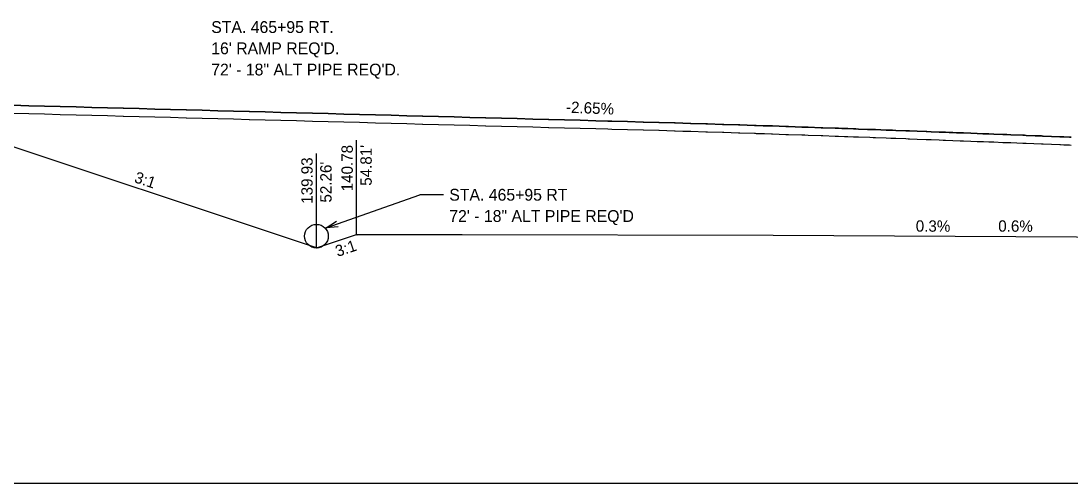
# Model space of a CAD drawing. Extents: x -26 to 4403, y -13 to 9578.
# Drawn here: x 1283.5 to 1350.1, y 7500 to 7529.3 of the extents above; entities that cross this region are included whole.
import ezdxf

# ---------------------------------------------------------------- set-up
doc = ezdxf.new("R2010")
doc.units = 0
for name, color, linetype in [('CONST_DCH', 7, 'Continuous'), ('CONST_LV3', 7, 'Continuous'), ('DTM_CORRIDOR', 7, 'Continuous'), ('DTM_P_FINISHED_GRADE', 7, 'Continuous'), ('DTM_X_GROUND', 7, 'Continuous'), ('XS_CELL', 7, 'Continuous'), ('XS_P_DR_GRAVEL', 7, 'Continuous'), ('XS_P_DRAINAGE', 7, 'Continuous'), ('XS_P_GROUND', 7, 'Continuous'), ('XS_P_TX_CLEARZONE', 7, 'Continuous'), ('XS_P_TX_FS_BS', 7, 'Continuous')]:
    doc.layers.add(name, color=color, linetype=linetype)

msp = doc.modelspace()

# ---------------------------------------------------------------- linework, layer by layer
at = {"layer": 'CONST_LV3'}
msp.add_lwpolyline([(1282.996, 7523.989), (1283.996, 7523.963), (1284.996, 7523.936), (1285.996, 7523.91), (1286.996, 7523.883), (1287.996, 7523.857), (1288.996, 7523.83), (1289.996, 7523.804), (1290.996, 7523.777), (1291.996, 7523.751), (1292.996, 7523.724), (1293.996, 7523.698), (1294.996, 7523.671), (1295.996, 7523.645), (1296.996, 7523.618), (1297.996, 7523.592), (1298.996, 7523.565), (1299.996, 7523.539), (1300.996, 7523.512), (1301.996, 7523.486), (1302.996, 7523.459), (1303.996, 7523.433), (1304.996, 7523.406), (1305.996, 7523.38), (1306.996, 7523.353), (1307.996, 7523.327), (1308.996, 7523.3), (1309.996, 7523.274), (1310.996, 7523.247), (1311.996, 7523.221), (1312.996, 7523.194), (1313.996, 7523.168), (1314.996, 7523.141), (1315.996, 7523.115), (1316.996, 7523.088), (1317.996, 7523.062), (1318.996, 7523.035), (1319.996, 7523.009), (1320.757, 7522.989), (1320.996, 7522.982), (1320.996, 7522.982), (1320.996, 7522.982), (1321.996, 7522.955), (1321.996, 7522.955), (1321.998, 7522.955), (1322.995, 7522.927), (1322.998, 7522.927), (1323.002, 7522.927), (1323.994, 7522.899), (1324.001, 7522.899), (1324.007, 7522.898), (1324.991, 7522.869), (1325.005, 7522.869), (1325.014, 7522.869), (1325.025, 7522.869), (1326.004, 7522.839), (1326.015, 7522.839), (1326.021, 7522.839), (1326.504, 7522.824), (1326.546, 7522.823), (1327.029, 7522.808), (1327.079, 7522.806), (1328.037, 7522.776), (1328.047, 7522.776), (1328.104, 7522.774), (1329.044, 7522.743), (1329.071, 7522.743), (1329.132, 7522.741), (1330.051, 7522.711), (1330.103, 7522.709), (1330.105, 7522.709), (1330.161, 7522.707), (1331.056, 7522.677), (1331.142, 7522.675), (1331.192, 7522.673), (1331.632, 7522.658), (1331.753, 7522.654), (1332.189, 7522.639), (1332.223, 7522.638), (1333.062, 7522.609), (1333.247, 7522.603), (1333.255, 7522.603), (1333.46, 7522.596), (1334.287, 7522.566), (1334.296, 7522.566), (1334.405, 7522.562), (1335.187, 7522.534), (1335.319, 7522.529), (1335.394, 7522.527), (1335.597, 7522.52), (1336.35, 7522.493), (1336.486, 7522.488), (1336.668, 7522.482), (1337.031, 7522.468), (1337.239, 7522.461), (1337.592, 7522.448), (1337.741, 7522.443), (1338.409, 7522.417), (1338.713, 7522.407), (1338.815, 7522.404), (1339.032, 7522.395), (1339.657, 7522.371), (1339.813, 7522.365), (1339.889, 7522.364), (1340.461, 7522.341), (1340.964, 7522.322), (1341.006, 7522.321), (1341.52, 7522.301), (1342.038, 7522.281), (1342.179, 7522.276), (1342.418, 7522.267), (1342.89, 7522.249), (1343.113, 7522.24), (1343.32, 7522.232), (1343.79, 7522.215), (1344.186, 7522.199), (1344.546, 7522.185), (1344.589, 7522.184), (1344.928, 7522.171), (1345.257, 7522.157), (1345.828, 7522.135), (1346.066, 7522.127), (1346.328, 7522.116), (1347.092, 7522.086), (1347.205, 7522.083), (1347.397, 7522.075), (1348.345, 7522.035), (1348.384, 7522.035), (1348.444, 7522.032), (1349.459, 7521.991), (1349.484, 7521.99), (1349.704, 7521.982), (1350.05, 7521.968), (1350.15, 7521.964)], dxfattribs=at)
at = {"layer": 'DTM_P_FINISHED_GRADE'}
msp.add_lwpolyline([(1283, 7523.989), (1283.996, 7523.963), (1284, 7523.963), (1284.996, 7523.936), (1285, 7523.936), (1285.996, 7523.91), (1286, 7523.91), (1286.996, 7523.883), (1287, 7523.883), (1287.996, 7523.857), (1288, 7523.857), (1288.996, 7523.83), (1289, 7523.83), (1289.996, 7523.804), (1290, 7523.804), (1290.996, 7523.777), (1291, 7523.777), (1291.996, 7523.751), (1292, 7523.751), (1292.996, 7523.724), (1293, 7523.724), (1293.996, 7523.698), (1294, 7523.698), (1294.996, 7523.671), (1295, 7523.671), (1295.996, 7523.645), (1296, 7523.645), (1296.996, 7523.618), (1297, 7523.618), (1297.996, 7523.592), (1298, 7523.592), (1298.996, 7523.565), (1299, 7523.565), (1299.996, 7523.539), (1300, 7523.539), (1300.996, 7523.512), (1301, 7523.512), (1301.996, 7523.486), (1302, 7523.486), (1302.996, 7523.459), (1303, 7523.459), (1303.996, 7523.433), (1304, 7523.433), (1304.996, 7523.406), (1305, 7523.406), (1305.996, 7523.38), (1306, 7523.38), (1306.996, 7523.353), (1307, 7523.353), (1307.996, 7523.327), (1308, 7523.327), (1308.996, 7523.3), (1309, 7523.3), (1309.996, 7523.274), (1310, 7523.274), (1310.996, 7523.247), (1311, 7523.247), (1311.996, 7523.221), (1312, 7523.221), (1312.996, 7523.194), (1313, 7523.194), (1313.996, 7523.168), (1314, 7523.168), (1314.996, 7523.141), (1315, 7523.141), (1315.996, 7523.115), (1316, 7523.115), (1316.996, 7523.088), (1317, 7523.088), (1317.996, 7523.062), (1318, 7523.062), (1318.996, 7523.035), (1319, 7523.035), (1319.996, 7523.009), (1320, 7523.009), (1320.757, 7522.989), (1320.996, 7522.982), (1320.996, 7522.982), (1321, 7522.982), (1321, 7522.982), (1321.996, 7522.955), (1321.996, 7522.955), (1322, 7522.955), (1322.002, 7522.955), (1322.995, 7522.927), (1322.998, 7522.927), (1323.001, 7522.927), (1323.005, 7522.927), (1323.994, 7522.899), (1324.001, 7522.899), (1324.004, 7522.898), (1324.011, 7522.898), (1324.991, 7522.869), (1325.005, 7522.869), (1325.008, 7522.869), (1325.017, 7522.869), (1325.507, 7522.854), (1325.521, 7522.854), (1326.004, 7522.839), (1326.015, 7522.839), (1326.019, 7522.839), (1326.025, 7522.838), (1326.98, 7522.809), (1327.029, 7522.808), (1327.032, 7522.807), (1327.083, 7522.806), (1328.037, 7522.776), (1328.047, 7522.776), (1328.051, 7522.775), (1328.108, 7522.774), (1329.044, 7522.743), (1329.072, 7522.743), (1329.075, 7522.743), (1329.135, 7522.741), (1330.051, 7522.711), (1330.103, 7522.709), (1330.106, 7522.709), (1330.109, 7522.709), (1330.164, 7522.707), (1330.617, 7522.692), (1330.697, 7522.69), (1331.142, 7522.675), (1331.145, 7522.674), (1331.195, 7522.673), (1332.06, 7522.643), (1332.189, 7522.639), (1332.193, 7522.639), (1332.226, 7522.638), (1333.062, 7522.609), (1333.247, 7522.603), (1333.25, 7522.603), (1333.258, 7522.603), (1333.463, 7522.595), (1334.287, 7522.566), (1334.296, 7522.566), (1334.299, 7522.566), (1334.408, 7522.562), (1335.187, 7522.534), (1335.319, 7522.529), (1335.394, 7522.527), (1335.397, 7522.527), (1335.774, 7522.513), (1335.983, 7522.506), (1336.35, 7522.493), (1336.486, 7522.488), (1336.489, 7522.488), (1336.671, 7522.482), (1337.38, 7522.455), (1337.592, 7522.448), (1337.595, 7522.448), (1337.744, 7522.443), (1338.409, 7522.417), (1338.713, 7522.407), (1338.716, 7522.407), (1338.817, 7522.403), (1339.035, 7522.395), (1339.657, 7522.371), (1339.813, 7522.365), (1339.889, 7522.364), (1339.892, 7522.364), (1340.391, 7522.344), (1340.964, 7522.322), (1341.006, 7522.321), (1341.008, 7522.321), (1341.274, 7522.31), (1341.788, 7522.291), (1342.038, 7522.281), (1342.179, 7522.276), (1342.181, 7522.276), (1342.656, 7522.258), (1343.113, 7522.24), (1343.32, 7522.232), (1343.322, 7522.231), (1343.792, 7522.215), (1344.186, 7522.199), (1344.546, 7522.185), (1344.589, 7522.184), (1344.59, 7522.184), (1344.929, 7522.171), (1345.258, 7522.157), (1345.828, 7522.135), (1345.829, 7522.135), (1346.067, 7522.127), (1346.328, 7522.116), (1347.092, 7522.086), (1347.093, 7522.086), (1347.206, 7522.083), (1347.305, 7522.079), (1348.279, 7522.038), (1348.345, 7522.035), (1348.384, 7522.035), (1348.384, 7522.035), (1349.433, 7521.992), (1349.484, 7521.99), (1349.704, 7521.982), (1349.704, 7521.982), (1350.05, 7521.968), (1350.15, 7521.964)], dxfattribs=at)
at = {"layer": 'DTM_X_GROUND'}
msp.add_lwpolyline([(1304.806, 7515.777), (1309.035, 7515.784), (1309.106, 7515.785), (1310.099, 7515.786), (1311.498, 7515.789), (1331.242, 7515.749), (1362.053, 7515.566), (1388.429, 7515.524), (1400, 7515.43)], dxfattribs=at)
at = {"layer": 'XS_CELL'}
msp.add_line((1250, 7500), (1400, 7500), dxfattribs=at)
at = {"layer": 'XS_P_DR_GRAVEL'}
for points in [[(1350.15, 7521.964), (1350.05, 7521.968), (1349.704, 7521.982), (1349.704, 7521.982), (1349.484, 7521.99), (1349.433, 7521.992), (1348.384, 7522.035), (1348.384, 7522.035), (1348.345, 7522.035), (1348.279, 7522.038), (1347.305, 7522.079), (1347.206, 7522.083), (1347.093, 7522.086), (1347.092, 7522.086), (1346.328, 7522.116), (1346.067, 7522.127), (1345.829, 7522.135), (1345.828, 7522.135), (1345.258, 7522.157), (1344.929, 7522.171), (1344.59, 7522.184), (1344.589, 7522.184), (1344.546, 7522.185), (1344.186, 7522.199), (1343.792, 7522.215), (1343.322, 7522.231), (1343.32, 7522.232), (1343.113, 7522.24), (1342.656, 7522.258), (1342.181, 7522.276), (1342.179, 7522.276), (1342.038, 7522.281), (1341.788, 7522.291), (1341.274, 7522.31), (1341.008, 7522.321), (1341.006, 7522.321), (1340.964, 7522.322), (1340.391, 7522.344), (1339.892, 7522.364), (1339.889, 7522.364), (1339.813, 7522.365), (1339.657, 7522.371), (1339.035, 7522.395), (1338.817, 7522.403), (1338.716, 7522.407), (1338.713, 7522.407), (1338.409, 7522.417), (1337.744, 7522.443), (1337.595, 7522.448), (1337.592, 7522.448), (1337.38, 7522.455), (1336.671, 7522.482), (1336.489, 7522.488), (1336.486, 7522.488), (1336.35, 7522.493), (1335.983, 7522.506), (1335.774, 7522.513), (1335.397, 7522.527), (1335.394, 7522.527), (1335.319, 7522.529), (1335.187, 7522.534), (1334.408, 7522.562), (1334.299, 7522.566), (1334.296, 7522.566), (1334.287, 7522.566), (1333.463, 7522.595), (1333.258, 7522.603), (1333.25, 7522.603), (1333.247, 7522.603), (1333.062, 7522.609), (1332.226, 7522.638), (1332.193, 7522.639), (1332.189, 7522.639), (1332.06, 7522.643), (1331.195, 7522.673), (1331.145, 7522.674), (1331.142, 7522.675), (1330.697, 7522.69), (1330.617, 7522.692), (1330.164, 7522.707), (1330.109, 7522.709), (1330.106, 7522.709), (1330.103, 7522.709), (1330.051, 7522.711), (1329.135, 7522.741), (1329.075, 7522.743), (1329.072, 7522.743), (1329.044, 7522.743), (1328.108, 7522.774), (1328.051, 7522.775), (1328.047, 7522.776), (1328.037, 7522.776), (1327.083, 7522.806), (1327.032, 7522.807), (1327.029, 7522.808), (1326.98, 7522.809), (1326.025, 7522.838), (1326.019, 7522.839), (1326.015, 7522.839), (1326.004, 7522.839), (1325.521, 7522.854), (1325.507, 7522.854), (1325.017, 7522.869), (1325.008, 7522.869), (1325.005, 7522.869), (1324.991, 7522.869), (1324.011, 7522.898), (1324.004, 7522.898), (1324.001, 7522.899), (1323.994, 7522.899), (1323.005, 7522.927), (1323.001, 7522.927), (1322.998, 7522.927), (1322.995, 7522.927), (1322.002, 7522.955), (1322, 7522.955), (1321.996, 7522.955), (1321.996, 7522.955), (1321, 7522.982), (1321, 7522.982), (1320.996, 7522.982), (1320.996, 7522.982), (1320.757, 7522.989), (1320.757, 7522.989), (1320, 7523.009), (1319.996, 7523.009), (1319, 7523.035), (1318.996, 7523.035), (1318, 7523.062), (1317.996, 7523.062), (1317, 7523.088), (1316.996, 7523.088), (1316, 7523.115), (1315.996, 7523.115), (1315, 7523.141), (1314.996, 7523.141), (1314, 7523.168), (1313.996, 7523.168), (1313, 7523.194), (1312.996, 7523.194), (1312, 7523.221), (1311.996, 7523.221), (1311, 7523.247), (1310.996, 7523.247), (1310, 7523.274), (1309.996, 7523.274), (1309, 7523.3), (1308.996, 7523.3), (1308, 7523.327), (1307.996, 7523.327), (1307, 7523.353), (1306.996, 7523.353), (1306, 7523.38), (1305.996, 7523.38), (1305, 7523.406), (1304.996, 7523.406), (1304, 7523.433), (1303.996, 7523.433), (1303, 7523.459), (1302.996, 7523.459), (1302, 7523.486), (1301.996, 7523.486), (1301, 7523.512), (1300.996, 7523.512), (1300, 7523.539), (1299.996, 7523.539), (1299, 7523.565), (1298.996, 7523.565), (1298, 7523.592), (1297.996, 7523.592), (1297, 7523.618), (1296.996, 7523.618), (1296, 7523.645), (1295.996, 7523.645), (1295, 7523.671), (1294.996, 7523.671), (1294, 7523.698), (1293.996, 7523.698), (1293, 7523.724), (1292.996, 7523.724), (1292, 7523.751), (1291.996, 7523.751), (1291, 7523.777), (1290.996, 7523.777), (1290, 7523.804), (1289.996, 7523.804), (1289, 7523.83), (1288.996, 7523.83), (1288, 7523.857), (1287.996, 7523.857), (1287, 7523.883), (1286.996, 7523.883), (1286, 7523.91), (1285.996, 7523.91), (1285, 7523.936), (1284.996, 7523.936), (1284, 7523.963), (1283.996, 7523.963), (1283, 7523.989)], [(1283, 7523.489), (1283.996, 7523.463), (1284, 7523.463), (1284.996, 7523.436), (1285, 7523.436), (1285.996, 7523.41), (1286, 7523.41), (1286.996, 7523.383), (1287, 7523.383), (1287.996, 7523.357), (1288, 7523.357), (1288.996, 7523.33), (1289, 7523.33), (1289.996, 7523.304), (1290, 7523.304), (1290.996, 7523.277), (1291, 7523.277), (1291.996, 7523.251), (1292, 7523.251), (1292.996, 7523.224), (1293, 7523.224), (1293.996, 7523.198), (1294, 7523.198), (1294.996, 7523.171), (1295, 7523.171), (1295.996, 7523.145), (1296, 7523.145), (1296.996, 7523.118), (1297, 7523.118), (1297.996, 7523.092), (1298, 7523.092), (1298.996, 7523.065), (1299, 7523.065), (1299.996, 7523.039), (1300, 7523.039), (1300.996, 7523.012), (1301, 7523.012), (1301.996, 7522.986), (1302, 7522.986), (1302.996, 7522.959), (1303, 7522.959), (1303.996, 7522.933), (1304, 7522.933), (1304.996, 7522.906), (1305, 7522.906), (1305.996, 7522.88), (1306, 7522.88), (1306.996, 7522.853), (1307, 7522.853), (1307.996, 7522.827), (1308, 7522.827), (1308.996, 7522.8), (1309, 7522.8), (1309.996, 7522.774), (1310, 7522.774), (1310.996, 7522.747), (1311, 7522.747), (1311.996, 7522.721), (1312, 7522.721), (1312.996, 7522.694), (1313, 7522.694), (1313.996, 7522.668), (1314, 7522.668), (1314.996, 7522.641), (1315, 7522.641), (1315.996, 7522.615), (1316, 7522.615), (1316.996, 7522.588), (1317, 7522.588), (1317.996, 7522.562), (1318, 7522.562), (1318.996, 7522.535), (1319, 7522.535), (1319.996, 7522.509), (1320, 7522.509), (1320.757, 7522.489), (1320.757, 7522.489), (1320.996, 7522.482), (1320.996, 7522.482), (1321, 7522.482), (1321, 7522.482), (1321.996, 7522.455), (1321.996, 7522.455), (1322, 7522.455), (1322.002, 7522.455), (1322.995, 7522.427), (1322.998, 7522.427), (1323.001, 7522.427), (1323.005, 7522.427), (1323.994, 7522.399), (1324.001, 7522.399), (1324.004, 7522.398), (1324.011, 7522.398), (1324.991, 7522.369), (1325.005, 7522.369), (1325.008, 7522.369), (1325.017, 7522.369), (1325.507, 7522.354), (1325.521, 7522.354), (1326.004, 7522.339), (1326.015, 7522.339), (1326.019, 7522.339), (1326.025, 7522.338), (1326.98, 7522.309), (1327.029, 7522.308), (1327.032, 7522.307), (1327.083, 7522.306), (1328.037, 7522.276), (1328.047, 7522.276), (1328.051, 7522.275), (1328.108, 7522.274), (1329.044, 7522.243), (1329.072, 7522.243), (1329.075, 7522.243), (1329.135, 7522.241), (1330.051, 7522.211), (1330.103, 7522.209), (1330.106, 7522.209), (1330.109, 7522.209), (1330.164, 7522.207), (1330.617, 7522.192), (1330.697, 7522.19), (1331.142, 7522.175), (1331.145, 7522.174), (1331.195, 7522.173), (1332.06, 7522.143), (1332.189, 7522.139), (1332.193, 7522.139), (1332.226, 7522.138), (1333.062, 7522.109), (1333.247, 7522.103), (1333.25, 7522.103), (1333.258, 7522.103), (1333.463, 7522.095), (1334.287, 7522.066), (1334.296, 7522.066), (1334.299, 7522.066), (1334.408, 7522.062), (1335.187, 7522.034), (1335.319, 7522.029), (1335.394, 7522.027), (1335.397, 7522.027), (1335.774, 7522.013), (1335.983, 7522.006), (1336.35, 7521.993), (1336.486, 7521.988), (1336.489, 7521.988), (1336.671, 7521.982), (1337.38, 7521.955), (1337.592, 7521.948), (1337.595, 7521.948), (1337.744, 7521.943), (1338.409, 7521.917), (1338.713, 7521.907), (1338.716, 7521.907), (1338.817, 7521.903), (1339.035, 7521.895), (1339.657, 7521.871), (1339.813, 7521.865), (1339.889, 7521.864), (1339.892, 7521.864), (1340.391, 7521.844), (1340.964, 7521.822), (1341.006, 7521.821), (1341.008, 7521.821), (1341.274, 7521.81), (1341.788, 7521.791), (1342.038, 7521.781), (1342.179, 7521.776), (1342.181, 7521.776), (1342.656, 7521.758), (1343.113, 7521.74), (1343.32, 7521.732), (1343.322, 7521.731), (1343.792, 7521.715), (1344.186, 7521.699), (1344.546, 7521.685), (1344.589, 7521.684), (1344.59, 7521.684), (1344.929, 7521.671), (1345.258, 7521.657), (1345.828, 7521.635), (1345.829, 7521.635), (1346.067, 7521.627), (1346.328, 7521.616), (1347.092, 7521.586), (1347.093, 7521.586), (1347.206, 7521.583), (1347.305, 7521.579), (1348.279, 7521.538), (1348.345, 7521.535), (1348.384, 7521.535), (1348.384, 7521.535), (1349.433, 7521.492), (1349.484, 7521.49), (1349.704, 7521.482), (1349.704, 7521.482), (1350.05, 7521.468), (1350.15, 7521.464)]]:
    msp.add_lwpolyline(points, dxfattribs=at)
at = {"layer": 'XS_P_DRAINAGE'}
for p in [(1302.875, 7516.205), (1310.313, 7518.306)]:
    msp.add_line(p, (1308.813, 7518.306), dxfattribs=at)
msp.add_lwpolyline([(1303.645, 7516.278), (1302.875, 7516.205), (1303.52, 7516.632)], dxfattribs=at)
msp.add_circle((1302.257, 7515.678), 0.75, dxfattribs=at)
at = {"layer": 'XS_P_GROUND'}
for points in [[(1302.257, 7514.928), (1302.134, 7514.969), (1280, 7522.346), (1279.961, 7522.356), (1272.446, 7524.235)], [(1302.257, 7514.928), (1304.806, 7515.777)]]:
    msp.add_lwpolyline(points, dxfattribs=at)
at = {"layer": 'XS_P_TX_CLEARZONE'}
for p, q in [((1304.806, 7515.777), (1304.806, 7521.777)), ((1302.257, 7514.928), (1302.257, 7520.928))]:
    msp.add_line(p, q, dxfattribs=at)

# ---------------------------------------------------------------- texts
at = {"layer": 'CONST_DCH'}
msp.add_text('X', height=0.12, dxfattribs=at).set_placement((1302.218, 7514.868))
at = {"layer": 'DTM_CORRIDOR'}
msp.add_text('X', height=0.12, dxfattribs=at).set_placement((1304.767, 7515.717))
at = {"layer": 'XS_P_DRAINAGE'}
for s, p in [('STA. 465+95 RT.', (1295.578, 7528.581)), ("16' RAMP REQ'D.", (1295.578, 7527.231)), ('72\' - 18" ALT PIPE REQ\'D.', (1295.578, 7525.881)), ('STA. 465+95 RT', (1310.688, 7517.931)), ('72\' - 18" ALT PIPE REQ\'D', (1310.688, 7516.581))]:
    msp.add_text(s, height=0.75, dxfattribs=at).set_placement(p)
at = {"layer": 'XS_P_TX_CLEARZONE'}
for s, p in [('140.78', (1304.566, 7518.525)), ("54.81'", (1305.766, 7518.876)), ('139.93', (1302.017, 7517.732)), ("52.26'", (1303.217, 7517.811))]:
    msp.add_text(s, height=0.72, rotation=90, dxfattribs=at).set_placement(p)
at = {"layer": 'XS_P_TX_FS_BS'}
for s, rotation, p in [('-2.65%', 357.70939, (1318.083, 7523.52)), ('3:1', 341.56677, (1290.643, 7519.115)), ('0.3%', 359.81461, (1340.295, 7515.963)), ('0.6%', 359.6589, (1345.53, 7515.964)), ('0.6%', 359.6589, (1345.53, 7515.964)), ('3:1', 18.43493, (1303.597, 7514.354))]:
    msp.add_text(s, height=0.72, rotation=rotation, dxfattribs=at).set_placement(p)

doc.saveas('drawing.dxf')
